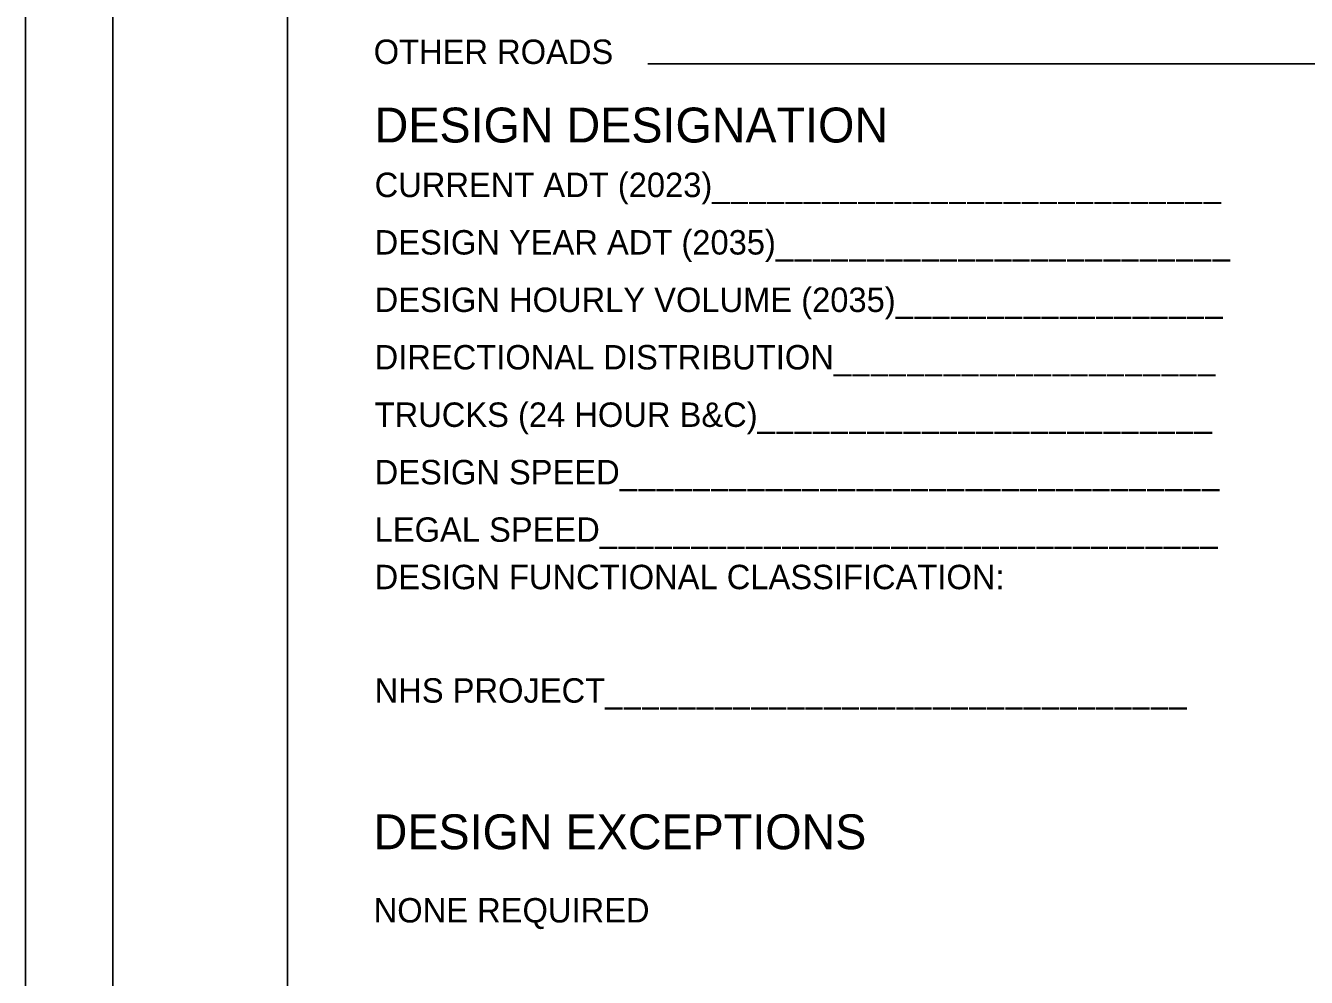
# Model space of a CAD drawing. Extents: x 0 to 34, y 0 to 22.
# Drawn here: x 0 to 7.34, y 5.64 to 11.1 of the extents above; entities that cross this region are included whole.
import ezdxf

# ---------------------------------------------------------------- set-up
doc = ezdxf.new("R2010")
doc.units = 0
for name, color, linetype in [('SH_Border', 7, 'Continuous'), ('SH_Cut_Line', 7, 'Continuous'), ('SH_Data', 7, 'Continuous'), ('SH_Text', 7, 'Continuous')]:
    doc.layers.add(name, color=color, linetype=linetype)

msp = doc.modelspace()

# ---------------------------------------------------------------- linework, layer by layer
at = {"layer": 'SH_Border'}
for points in [[(0.5, 21.5), (1.5, 21.5), (1.5, 0.5), (0.5, 0.5)], [(1.5, 21.5), (33.5, 21.5), (33.5, 0.5), (1.5, 0.5)]]:
    msp.add_lwpolyline(points, close=True, dxfattribs=at)
at = {"layer": 'SH_Cut_Line'}
msp.add_lwpolyline([(0, 0), (34, 0), (34, 22), (0, 22)], close=True, dxfattribs=at)
at = {"layer": 'SH_Data'}
msp.add_line((7.7, 10.8767), (3.5657, 10.8767), dxfattribs=at)

# ---------------------------------------------------------------- texts
msp.add_text('DESIGN DESIGNATION', height=0.2, dxfattribs=at).set_placement((2, 10.4265))
at = {"layer": 'SH_Text'}
for s, height, p in [('OTHER ROADS', 0.14, (1.9944, 10.8767)), ('CURRENT ADT (2023)____________________________', 0.14, (2, 10.1136)), ('DESIGN YEAR ADT (2035)_________________________', 0.14, (2, 9.7841)), ('DESIGN HOURLY VOLUME (2035)__________________', 0.14, (2, 9.4547)), ('DIRECTIONAL DISTRIBUTION_____________________', 0.14, (2, 9.1253)), ('TRUCKS (24 HOUR B&C)_________________________', 0.14, (2, 8.7959)), ('DESIGN SPEED_________________________________', 0.14, (2, 8.4665)), ('LEGAL SPEED__________________________________', 0.14, (2, 8.1371)), ('DESIGN FUNCTIONAL CLASSIFICATION:', 0.14, (2, 7.8653)), ('NHS PROJECT________________________________', 0.14, (2, 7.2147)), ('DESIGN EXCEPTIONS', 0.2, (1.9944, 6.3744)), ('NONE REQUIRED', 0.14, (1.9944, 5.9544))]:
    msp.add_text(s, height=height, dxfattribs=at).set_placement(p)

doc.saveas('drawing.dxf')
